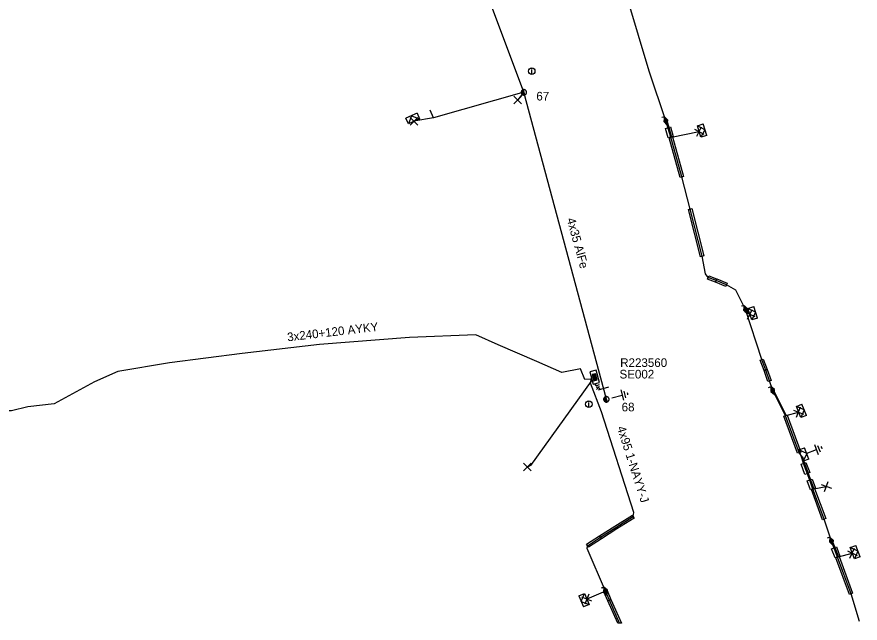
# Model space of a CAD drawing. Extents: x -536148 to -535465, y -1201639 to -1201298.
# Drawn here: x -535608.3 to -535510.8, y -1201637.8 to -1201567.7 of the extents above; entities that cross this region are included whole.
import ezdxf

# ---------------------------------------------------------------- set-up
doc = ezdxf.new("R2010")
doc.units = 0
for name, color, linetype in [('CHRAN_NN', 7, 'Continuous'), ('CIZÍ_NADZEM_POPIS', 7, 'Continuous'), ('CIZÍ_PODZEM', 7, 'Continuous'), ('CIZÍ_PODZEM_POPIS', 7, 'Continuous'), ('DOPLŇ_POPISY', 7, 'Continuous'), ('ELE_EON', 7, 'Continuous'), ('ELE_EON_POPIS', 7, 'Continuous'), ('KN_HRAN_PARCEL_NEVIDITELNÁ', 7, 'Continuous'), ('KN_HRAN_PODZEM', 7, 'Continuous'), ('KN_HRAN_POHYBLIVÁ', 7, 'Continuous'), ('KN_VKP_HRAN_', 7, 'Continuous'), ('KN_VKP_HRAN_NEZNATELNÁ', 7, 'Continuous'), ('KN_VKP_HRAN_PARCEL_NEVIDITELNÁ', 7, 'Continuous'), ('KN_VKP_HRAN_SPORNÁ', 7, 'Continuous'), ('OP KABELU NN', 7, 'Continuous'), ('PK_HRAN_POHYBLIVÁ', 7, 'Continuous'), ('PLG_EXPORT_GPE', 7, 'Continuous'), ('PODZEM_NN_POPIS', 7, 'Continuous'), ('PROJEKT', 7, 'Continuous'), ('RÁMEČEK', 7, 'Continuous'), ('SDEL_EON_POPIS', 7, 'Continuous'), ('ZRUŠENO', 7, 'Continuous')]:
    doc.layers.add(name, color=color, linetype=linetype)

# ---------------------------------------------------------------- blocks, each defined once
blk = doc.blocks.new('NN440')
at = {"layer": 'ELE_EON_POPIS'}
for points in [[(0.63, 0), (0.63, 0.06), (0.62, 0.13), (0.6, 0.19), (0.58, 0.25), (0.55, 0.31), (0.51, 0.37), (0.47, 0.42), (0.42, 0.46), (0.37, 0.51), (0.32, 0.54), (0.26, 0.57), (0.2, 0.59), (0.13, 0.61), (0.07, 0.62), (0, 0.63), (-0.06, 0.62), (-0.13, 0.61), (-0.19, 0.59), (-0.26, 0.57), (-0.31, 0.54), (-0.37, 0.51), (-0.42, 0.46), (-0.47, 0.42), (-0.51, 0.37), (-0.54, 0.31), (-0.57, 0.25), (-0.6, 0.19), (-0.62, 0.13), (-0.63, 0.06), (-0.63, 0), (-0.63, -0.07), (-0.62, -0.14), (-0.6, -0.2), (-0.57, -0.26), (-0.54, -0.32), (-0.51, -0.37), (-0.47, -0.43), (-0.42, -0.47), (-0.37, -0.51), (-0.31, -0.55), (-0.26, -0.58), (-0.19, -0.6), (-0.13, -0.62), (-0.06, -0.63), (0, -0.63), (0.07, -0.63), (0.13, -0.62), (0.2, -0.6), (0.26, -0.58), (0.32, -0.55), (0.37, -0.51), (0.42, -0.47), (0.47, -0.43), (0.51, -0.37), (0.55, -0.32), (0.58, -0.26), (0.6, -0.2), (0.62, -0.14), (0.63, -0.07), (0.63, 0)], [(-0.63, 0), (0.63, 0)], [(-0.6, -0.18), (0.57, -0.18)], [(-0.51, -0.32), (0.5, -0.32)], [(-0.37, -0.47), (0.35, -0.47)]]:
    blk.add_lwpolyline(points, dxfattribs=at)
blk = doc.blocks.new('NN840')
at = {"layer": 'RÁMEČEK'}
for points in [[(0.003, 0.619), (0.003, -0.631)], [(-0.745, -0.71), (-0.745, -0.66)], [(-0.73, -0.764), (-0.745, -0.71)], [(-0.657, -0.798), (-0.73, -0.764)], [(-0.627, -0.798), (-0.657, -0.798)], [(-0.558, -0.764), (-0.627, -0.798)], [(-0.538, -0.71), (-0.558, -0.764)], [(-0.538, -0.385), (-0.538, -0.71)], [(-0.332, -0.385), (-0.332, -0.798)], [(-0.332, -0.641), (-0.125, -0.385)], [(-0.263, -0.557), (-0.091, -0.798)]]:
    blk.add_lwpolyline(points, dxfattribs=at)
blk = doc.blocks.new('NN770')
at = {"layer": 'CIZÍ_PODZEM_POPIS'}
for p, q in [((0.002, 0.187), (0.002, 0.263)), ((0.002, -0.276), (0.002, 0.111))]:
    blk.add_line(p, q, dxfattribs=at)
blk.add_circle((0, -0.008), 0.375, dxfattribs=at)
blk = doc.blocks.new('NN880')
at = {"layer": 'SDEL_EON_POPIS'}
for points in [[(0.001, 0.248), (-0.499, 0)], [(0.001, 0.185), (-0.373, 0)], [(0.001, 0.122), (-0.247, 0)], [(0.001, 0.059), (-0.125, 0)], [(0.501, 0), (0.001, 0.248)], [(0.375, 0), (0.001, 0.185)], [(0.249, 0), (0.001, 0.122)], [(0.127, 0), (0.001, 0.059)], [(-0.566, -0.13), (-0.436, -0.13)], [(-0.499, 0), (0.001, -0.252)], [(-0.499, -0.13), (-0.499, -0.327)], [(-0.373, 0), (0.001, -0.189)], [(-0.247, 0), (0.001, -0.126)], [(-0.125, 0), (0.001, -0.063)], [(0.001, -0.252), (0.501, 0)], [(0.001, -0.189), (0.375, 0)], [(0.001, -0.126), (0.249, 0)], [(0.001, -0.063), (0.127, 0)]]:
    blk.add_lwpolyline(points, dxfattribs=at)
blk = doc.blocks.new('NN800')
at = {"layer": 'ELE_EON'}
for points in [[(-0.442, 0.442), (0.442, -0.442)], [(-0.442, -0.442), (0.442, 0.442)]]:
    blk.add_lwpolyline(points, dxfattribs=at)
blk = doc.blocks.new('NN620')
at = {"layer": 'CIZÍ_NADZEM_POPIS'}
for points in [[(0.752, 0.004), (-0.748, 0.004)], [(-0.748, 0.004), (-0.748, -0.746)], [(0.752, -0.746), (0.752, 0.004)], [(-0.748, -0.746), (0.752, -0.746)], [(0.368, -0.18), (-0.376, -0.18)], [(-0.376, -0.18), (-0.376, -0.558)], [(-0.376, -0.558), (0.368, -0.558)], [(0.321, -0.227), (-0.329, -0.227)], [(-0.329, -0.227), (-0.329, -0.51)], [(-0.329, -0.51), (0.321, -0.51)], [(0.274, -0.274), (-0.281, -0.274)], [(-0.281, -0.274), (-0.281, -0.463)], [(-0.281, -0.463), (0.274, -0.463)], [(0.227, -0.321), (-0.234, -0.321)], [(-0.234, -0.321), (-0.234, -0.416)], [(-0.234, -0.416), (0.227, -0.416)], [(-0.193, -0.369), (0.185, -0.369)], [(0.227, -0.416), (0.227, -0.321)], [(0.274, -0.463), (0.274, -0.274)], [(0.321, -0.51), (0.321, -0.227)], [(0.368, -0.558), (0.368, -0.18)]]:
    blk.add_lwpolyline(points, dxfattribs=at)
blk = doc.blocks.new('NN630')
at = {"layer": 'CIZÍ_PODZEM'}
for points in [[(-0.003, -0.7), (-0.703, 0)], [(-0.703, -0.7), (-0.703, 0), (0.697, 0), (0.697, -0.7)], [(-0.703, -0.7), (0.697, -0.7)], [(-0.003, -0.7), (0.697, 0)]]:
    blk.add_lwpolyline(points, dxfattribs=at)
blk = doc.blocks.new('NN810')
at = {"layer": 'PLG_EXPORT_GPE'}
for points in [[(0.004, -0.64), (0.004, -1.89)], [(0.629, -1.89), (-0.621, -1.89)], [(0.388, -2.2), (-0.399, -2.2)], [(0.004, -2.515), (-0.124, -2.515)], [(0.137, -2.515), (0.004, -2.515)]]:
    blk.add_lwpolyline(points, dxfattribs=at)
blk = doc.blocks.new('NN510')
at = {"layer": 'ELE_EON_POPIS'}
blk.add_lwpolyline([(0.001, 0.002), (0.001, 0.939)], dxfattribs=at)

msp = doc.modelspace()

# ---------------------------------------------------------------- linework, layer by layer
at = {"layer": 'CHRAN_NN'}
for points in [[(-535549.68, -1201576.4), (-535550.393, -1201577.274)], [(-535541.747, -1201609.787), (-535541.905, -1201609.829), (-535548.92, -1201619.609), (-535549.274, -1201619.769)]]:
    msp.add_lwpolyline(points, dxfattribs=at)
at = {"layer": 'CIZÍ_NADZEM_POPIS'}
msp.add_lwpolyline([(-535549.68, -1201576.4), (-535560.156, -1201579.338), (-535562.398, -1201579.752)], dxfattribs=at)
at = {"layer": 'ELE_EON'}
msp.add_lwpolyline([(-535540.143, -1201611.931), (-535549.68, -1201576.4), (-535561.545, -1201544.626)], dxfattribs=at)
at = {"layer": 'KN_HRAN_PARCEL_NEVIDITELNÁ'}
for points in [[(-535532.743, -1201580.414), (-535532.413, -1201581.514), (-535532.987, -1201581.686), (-535533.317, -1201580.586)], [(-535531.623, -1201586.243), (-535532.893, -1201581.653), (-535532.507, -1201581.547), (-535531.237, -1201586.137)], [(-535529.264, -1201595.43), (-535530.664, -1201589.96), (-535530.276, -1201589.86), (-535528.876, -1201595.33)], [(-535528.311, -1201597.652), (-535527.391, -1201597.992), (-535527.529, -1201598.368), (-535528.449, -1201598.028)], [(-535526.317, -1201598.875), (-535527.537, -1201598.365), (-535527.383, -1201597.995), (-535526.163, -1201598.505)], [(-535521.993, -1201607.268), (-535521.533, -1201608.468), (-535521.907, -1201608.612), (-535522.367, -1201607.412)], [(-535521.459, -1201609.877), (-535521.909, -1201608.607), (-535521.531, -1201608.473), (-535521.081, -1201609.743)], [(-535519.252, -1201613.761), (-535517.672, -1201618.031), (-535518.048, -1201618.169), (-535519.628, -1201613.899)], [(-535517.058, -1201619.247), (-535516.628, -1201620.417), (-535517.192, -1201620.623), (-535517.622, -1201619.453)], [(-535516.338, -1201621.179), (-535515.968, -1201622.209), (-535516.532, -1201622.411), (-535516.902, -1201621.381)], [(-535515.137, -1201625.88), (-535516.437, -1201622.38), (-535516.063, -1201622.24), (-535514.763, -1201625.74)], [(-535540.928, -1201627.731), (-535539.157, -1201626.601), (-535537.136, -1201625.331), (-535536.924, -1201625.669), (-535538.943, -1201626.939), (-535540.712, -1201628.069)], [(-535542.438, -1201628.702), (-535540.928, -1201627.732), (-535540.712, -1201628.068), (-535542.222, -1201629.038)], [(-535513.529, -1201629.015), (-535513.129, -1201630.085), (-535513.691, -1201630.295), (-535514.091, -1201629.225)], [(-535512.038, -1201634.509), (-535513.598, -1201630.259), (-535513.222, -1201630.121), (-535511.662, -1201634.371)], [(-535540.066, -1201634.051), (-535539.616, -1201635.101), (-535539.984, -1201635.259), (-535540.434, -1201634.209)], [(-535538.836, -1201637.835), (-535539.983, -1201635.261), (-535539.617, -1201635.099), (-535538.399, -1201637.832)]]:
    msp.add_lwpolyline(points, close=True, dxfattribs=at)
at = {"layer": 'PODZEM_NN_POPIS'}
for points in [[(-535533.26, -1201579.71), (-535533.164, -1201579.682), (-535532.934, -1201580.472), (-535532.601, -1201581.58), (-535529.41, -1201580.94)], [(-535524.06, -1201601.54), (-535523.55, -1201602.08)], [(-535520.91, -1201610.91), (-535520.821, -1201610.865), (-535519.342, -1201613.802), (-535517.91, -1201613.4)], [(-535517.62, -1201618.44), (-535517.471, -1201618.585), (-535517.245, -1201619.318), (-535516.816, -1201620.485), (-535516.526, -1201621.245), (-535516.151, -1201622.291), (-535514.71, -1201622.01)], [(-535514.11, -1201628.34), (-535514.017, -1201628.304), (-535513.716, -1201629.085), (-535513.313, -1201630.164), (-535511.7, -1201629.74)], [(-535540.25, -1201634.13), (-535542.41, -1201635.05)]]:
    msp.add_lwpolyline(points, dxfattribs=at)
at = {"layer": 'PROJEKT'}
for points in [[(-535510.853, -1201637.663), (-535511.85, -1201634.44), (-535513.41, -1201630.19), (-535514.11, -1201628.34), (-535514.95, -1201625.81), (-535516.25, -1201622.31), (-535516.62, -1201621.28), (-535517.34, -1201619.35), (-535517.62, -1201618.44), (-535517.86, -1201618.1), (-535519.44, -1201613.83), (-535520.91, -1201610.91), (-535521.27, -1201609.81), (-535521.72, -1201608.54), (-535522.18, -1201607.34), (-535524.06, -1201601.54), (-535525.16, -1201599.28), (-535526.24, -1201598.69), (-535527.46, -1201598.18), (-535528.38, -1201597.84), (-535528.66, -1201597.39), (-535529.07, -1201595.38), (-535530.47, -1201589.91), (-535531.43, -1201586.19), (-535532.7, -1201581.6), (-535533.26, -1201579.71), (-535535.21, -1201573.95), (-535537.66, -1201565.65)], [(-535541.81, -1201609.568), (-535541.94, -1201609.6), (-535542.62, -1201609.63), (-535543.14, -1201608.42), (-535545.31, -1201608.81), (-535548.18, -1201607.57), (-535552.64, -1201605.64), (-535555.25, -1201604.46), (-535562.9, -1201604.76), (-535573.31, -1201605.57), (-535582.28, -1201606.62), (-535590.67, -1201607.71), (-535596.64, -1201608.7), (-535599.34, -1201609.92), (-535604.02, -1201612.44), (-535607.05, -1201612.79), (-535608.95, -1201613.25), (-535609.8, -1201613.28), (-535609.91, -1201612.61), (-535609.923, -1201612.445)], [(-535538.617, -1201637.833), (-535539.8, -1201635.18), (-535540.25, -1201634.13), (-535542.38, -1201629.18), (-535542.33, -1201628.87), (-535540.82, -1201627.9), (-535539.05, -1201626.77), (-535537.03, -1201625.5), (-535536.98, -1201625.03), (-535540.69, -1201613.39), (-535541.98, -1201610.07), (-535541.85, -1201609.47)]]:
    msp.add_lwpolyline(points, dxfattribs=at)

# ---------------------------------------------------------------- block references
at = {"layer": 'DOPLŇ_POPISY', "xscale": 0.5}
for p, yscale, rotation in [((-535549.681, -1201576.401), 0.5, -74.97204328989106), ((-535540.143, -1201611.931), 0.49999999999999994, -74.66063332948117)]:
    msp.add_blockref('NN440', p, dxfattribs=dict(at, yscale=yscale, rotation=rotation))
at = {"layer": 'DOPLŇ_POPISY', "rotation": 23.575777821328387}
msp.add_blockref('NN510', (-535560.156, -1201579.338), dxfattribs=at)
at = {"layer": 'KN_HRAN_PODZEM'}
for p, rotation in [((-535533.26, -1201579.71), -73.4956386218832), ((-535524.06, -1201601.54), -72.04052390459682), ((-535520.91, -1201610.91), -63.278189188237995), ((-535514.11, -1201628.34), -69.27444117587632), ((-535540.25, -1201634.13), -66.8014094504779)]:
    msp.add_blockref('NN880', p, dxfattribs=dict(at, rotation=rotation))
at = {"layer": 'KN_HRAN_POHYBLIVÁ', "rotation": -74.91515517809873}
msp.add_blockref('NN840', (-535540.477, -1201610.693), dxfattribs=at)
at = {"layer": 'KN_VKP_HRAN_NEZNATELNÁ'}
for p in [(-535550.393, -1201577.274), (-535562.398, -1201579.752), (-535549.274, -1201619.769)]:
    msp.add_blockref('NN800', p, dxfattribs=at)
for p, rotation in [((-535529.41, -1201580.94), 17.59463414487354), ((-535523.55, -1201602.08), 18.800764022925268), ((-535517.91, -1201613.4), 23.30469923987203), ((-535514.71, -1201622.01), 24.368116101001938), ((-535511.7, -1201629.74), 19.72061178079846), ((-535542.41, -1201635.05), -156.82749636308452)]:
    msp.add_blockref('NN800', p, dxfattribs=dict(at, rotation=rotation))
at = {"layer": 'KN_VKP_HRAN_SPORNÁ'}
for p, rotation in [((-535562.398, -1201579.752), -156.26956385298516), ((-535529.41, -1201580.94), 107.36766352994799), ((-535523.55, -1201602.08), 108.32943184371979), ((-535517.91, -1201613.4), 112.15896377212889), ((-535517.62, -1201618.44), 111.25050554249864), ((-535511.7, -1201629.74), 110.947730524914), ((-535542.41, -1201635.05), -66.87801251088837)]:
    msp.add_blockref('NN630', p, dxfattribs=dict(at, rotation=rotation))
at = {"layer": 'OP KABELU NN', "rotation": 105.02654440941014}
msp.add_blockref('NN620', (-535541.86, -1201609.469), dxfattribs=at)
at = {"layer": 'PK_HRAN_POHYBLIVÁ'}
for p in [(-535548.773, -1201573.949), (-535542.17, -1201612.486)]:
    msp.add_blockref('NN770', p, dxfattribs=at)
at = {"layer": 'RÁMEČEK'}
for p, rotation in [((-535540.143, -1201611.931), 105.08484482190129), ((-535517.62, -1201618.44), 111.25050554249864)]:
    msp.add_blockref('NN810', p, dxfattribs=dict(at, rotation=rotation))

# ---------------------------------------------------------------- texts
at = {"layer": 'ELE_EON_POPIS'}
msp.add_text('4x35 AlFe', height=1, rotation=285.276, dxfattribs=at).set_placement((-535544.736, -1201591.074))
at = {"layer": 'KN_VKP_HRAN_'}
msp.add_text('SE002', height=1, dxfattribs=at).set_placement((-535538.624, -1201609.52))
at = {"layer": 'KN_VKP_HRAN_PARCEL_NEVIDITELNÁ'}
msp.add_text('R223560', height=1, dxfattribs=at).set_placement((-535538.543, -1201608.187))
at = {"layer": 'PLG_EXPORT_GPE'}
for s, p in [('67', (-535548.242, -1201577.35)), ('68', (-535538.377, -1201613.325))]:
    msp.add_text(s, height=1, dxfattribs=at).set_placement(p)
at = {"layer": 'ZRUŠENO'}
for s, rotation, p in [('3x240+120 AYKY', 6.676, (-535576.999, -1201605.229)), ('4x95 1-NAYY-J', 287.679, (-535538.927, -1201615.206))]:
    msp.add_text(s, height=1, rotation=rotation, dxfattribs=at).set_placement(p)

doc.saveas('drawing.dxf')
